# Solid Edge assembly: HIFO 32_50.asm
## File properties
Title: Zylinder
Author: ahadarics
Template: iso assembly.asm
Last saved by: ahadarics
Revision: 19
Application: Solid Edge
Username: ahadarics
Dokumentum tartalom típus: 1
Document Number: HIFO 32/50
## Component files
Profilrohr 32_50.par
Kit_1.par
Mutter.par
Kit_2.par
Kolbenstange 32_50.par
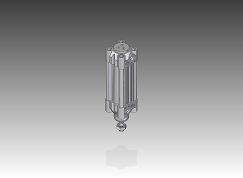
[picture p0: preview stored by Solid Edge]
